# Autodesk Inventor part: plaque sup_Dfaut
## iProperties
Created: 2007-07
Part Number: plaque sup_Dfaut
Document SubType Name: Modeling
Designer: EF
Density: 1 g/cm^3
Author: EF
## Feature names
1. Base1
